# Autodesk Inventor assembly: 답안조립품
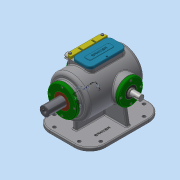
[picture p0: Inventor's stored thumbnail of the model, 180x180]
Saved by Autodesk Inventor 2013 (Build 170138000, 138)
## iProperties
Created: 2019-10
Part Number: 답안조립품
Document SubType Name: Assembly
Designer: Administrator
Author: Administrator
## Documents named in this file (17)
- C:\Users\Administrator\Desktop\391004V1044\답안조립품.iam
- C:\Users\Administrator\Desktop\391004V1044\본체.ipt
- C:\Users\Administrator\Desktop\391004V1044\가변스프링.ipt
- C:\Users\Administrator\Desktop\391004V1044\개스킷 A.ipt
- C:\Users\Administrator\Desktop\391004V1044\개스킷 B.ipt
- C:\Users\Administrator\Desktop\391004V1044\고정플레이트.ipt
- C:\Users\Administrator\Desktop\391004V1044\베어링 6205.ipt
- 베어링 6205.ipt
- C:\Users\Administrator\Desktop\391004V1044\볼트 M4x0.7.ipt
- C:\Users\Administrator\Desktop\391004V1044\부시.ipt
- C:\Users\Administrator\Desktop\391004V1044\상부커버.ipt
- C:\Users\Administrator\Desktop\391004V1044\슬라이드 커버.ipt
- C:\Users\Administrator\Desktop\391004V1044\슬라이드.ipt
- C:\Users\Administrator\Desktop\391004V1044\오일 실 25 38 8.ipt
- C:\Users\Administrator\Desktop\391004V1044\육각머리볼트 M4.ipt
- C:\Users\Administrator\Desktop\391004V1044\축 커버.ipt
- C:\Users\Administrator\Desktop\391004V1044\편심축.ipt
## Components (17 placed, 5 different names)
1. 가변스프링:1
2. 개스킷 A:1
3. 개스킷 B:1
4. 고정플레이트:1
5. 개스킷 B:2
6. M4x0.7:1
7. M4x0.7:4
8. M4x0.7:5
9. M4x0.7:6
10. M4x0.7:3
11. M4x0.7:7
12. M4x0.7:8
13. M4x0.7:9
14. M4x0.7:2
15. M4x0.7:10
16. M4x0.7:11
17. M4x0.7:12
